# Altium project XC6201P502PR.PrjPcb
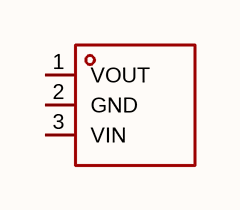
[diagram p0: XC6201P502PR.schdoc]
1 sheet, 1 parts. Net scope: global (net labels, ports and power ports of the same name join across sheets).

## Sheet XC6201P502PR.schdoc
size 127 x 101 mm

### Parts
U?  xc6201p502pr  [SOT-89-3_L4.5-W2.5-P1.50-LS4.2-BR]  (value not drawn)

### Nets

Not connected (* = marked no-connect by the designer): U? 1(VOUT) 2(GND) 3(VIN)

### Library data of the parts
U? = xc6201p502pr: 输出极性:正极;工作电压:12V;输出电压:5V;输出电流:300mA;电源纹波抑制比(PSRR):33dB@(1kHz);输出类型:固定;; Manufacturer: TECH PUBLIC(台舟); AddInBom: yes; ModelId: 6db690b7897d4d18a30d90c1b89525ee; ModelName: SOT-89-3_L4.3-W2.5-H1.6-LS4.1-P1.50; ModelTransform: 161.417,169.291,0,180,0,0,-18.661,0,0; Output Configuration: 正极; Voltage - Supply: 12V; Output Voltage: 5V; Output Current: 300mA; Voltage Dropout: 150mV@(100mA); standby current: 1.5uA; Output Type: 固定; Number of Outputs: 1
